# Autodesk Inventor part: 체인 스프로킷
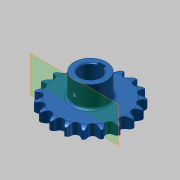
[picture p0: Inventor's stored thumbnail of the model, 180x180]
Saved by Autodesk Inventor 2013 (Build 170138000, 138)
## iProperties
Created: 2014-11
Part Number: 체인 스프로킷
Material: 강
Document SubType Name: Modeling
Designer: KYOUNG IL JANG
Density: 7.85 g/cm^3
Mass: 738.264 g
Surface Area: 236.923 cm^2
Volume: 94.0463 cm^3
CustomPartVersion: 1
Company: 한국ATC센터
Author: KYOUNG IL JANG
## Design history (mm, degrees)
sketch "이론적 톱니 프로파일"
  geometry: L1 (0, 0)-(0, 45.567); L2 (0, 0)-(14.795, 43.098); L3 (0, 45.567)-(14.795, 43.098); L4 (0, 45.567)-(5.661, 50.015); L5 (5.661, 50.015)-(-5.141, 45.406); L6 (-12.428, 43.493)-(-5.573, 46.417); L7 (-5.141, 45.406)-(-5.573, 46.417); L8 (5.573, 46.417)-(5.141, 45.406); L9 (0, 0)-(8.138, 48.771); A1 r 45.567 centre (0, 0) between (0, 45.567) and (14.795, 43.098); A2 r 49.445 centre (0, 0) between (7.302, 48.903) and (-7.302, 48.903); A3 r 4.545 centre (0, 45.567) between (-3.574, 42.758) and (3.574, 42.758); A4 r 7.453 centre (12.428, 43.493) between (7.302, 48.903) and (5.573, 46.417); A5 r 7.453 centre (-12.428, 43.493) between (-5.573, 46.417) and (-7.302, 48.903); A6 r 11.745 centre (5.661, 50.015) between (-5.141, 45.406) and (-3.574, 42.758); A7 r 11.745 centre (-5.661, 50.015) between (3.574, 42.758) and (5.141, 45.406); 2 further points
  constraints: 18 end point, 15 point on circle, 7 centre point, 3 coincident, 3 point on line, 3 symmetric about line, 3 tangent, 1 equal radius, 1 midpoint, 1 parallel, 1 vertical, 1 other
  dimensions: "d0" = 91.13301 diameter of A1 (computed from da_p, da_z); "d2" = 18.9474 deg angle of L2 L1 (computed from da_z); "d3" = 4.545 radius of A3 (= 0.5 x da_Dr + da_SC); "d10" = 128.158 deg angle of L4 L1 (computed from da_z); "d11" = 15.0526 deg angle of L5 L4 (computed from da_z); "d12" = 7.2 distance of L3.start L4.end (= 0.8 x da_Dr); "d13" = 11.745 distance of L4.end L5.end (= 1.3 x da_Dr + da_SC); "d14" = 12.6 distance of A4.centre L1.end (= 1.4 x da_Dr); "d23" = 4.5 distance from line of L9.end L3 (= da_Ha)
sketch "톱니 프로파일"
  geometry: L1 (0, 0)-(0, 45.567); L2 (0, 45.567)-(4.203, 43.837); L3 (0, 45.567)-(-4.203, 43.837); A1 r 4.545 centre (0, 45.567) between (-4.203, 43.837) and (4.203, 43.837); A2 r 22.68 centre (25.176, 35.206) between (7.12, 48.93) and (4.203, 43.837); A3 r 22.68 centre (-25.176, 35.206) between (-4.203, 43.837) and (-7.12, 48.93); A4 r 49.445 centre (0, 0) between (-7.12, 48.93) and (7.12, 48.93) reference; 1 further point
  constraints: 9 point on circle, 6 end point, 3 centre point, 2 tangent, 1 coincident, 1 equal radius, 1 vertical, 1 other
  dimensions: "d44" = 135.263 deg angle of L3 L2 (= da_Alfa); "d45" = 22.68 radius of A2 (= da_Re); "d46" = 4.545 radius of A1 (= da_Ri)
sketch "단면 프로파일"
  geometry: L1 (49.445, 0)-(-49.445, 0) reference; L2 (33.265, 6.65)-(-33.265, 6.65); L3 (-33.265, 6.65)-(-33.265, -6.65); L4 (-33.265, -6.65)-(33.265, -6.65); L5 (33.265, -6.65)-(33.265, 6.65); L6 (33.265, 6.65)-(49.445, 6.65); L7 (49.445, 6.65)-(49.445, -6.65); L8 (49.445, -6.65)-(33.265, -6.65); L9 (33.265, -6.65)-(33.265, 6.65); L10 (42.183, 6.65)-(0, 6.65); L11 (0, 6.65)-(0, -6.65); L12 (0, -6.65)-(42.183, -6.65); L13 (0, 6.65)-(0, -6.65); L14 (49.445, 4.775)-(49.445, -4.775); A1 r 15 centre (42.183, -8.35) between (49.445, 4.775) and (42.183, 6.65); A2 r 15 centre (42.183, 8.35) between (42.183, -6.65) and (49.445, -4.775); 2 further points
  constraints: 26 end point, 7 midpoint, 5 perpendicular, 4 parallel, 4 point on circle, 3 point on line, 3 symmetric about line, 2 centre point, 2 horizontal, 2 tangent, 1 collinear, 1 other
  dimensions: "d30" = 13.3 distance between parallel lines of L8 L6 (= da_Bf); "d31" = 66.53007 distance between parallel lines of L3 L5 (= da_Ds); "d32" = 13.3 distance between parallel lines of L4 L2 (= da_Bs); "d33" = 1.875 distance from line of L14.start L6 (= da_Ba); "d34" = 15 radius of A1 (= da_Rx); "d43" = 6.65 distance between parallel lines of L4 L1 (computed from da_k, da_pt, da_Bs)
revolve "슈라우드" stored, may be unused: angle "d36" = 90 deg
revolve "스트랜드" stored, may be unused: angle "d37" = 90 deg
extrude "이론적 톱니" cut sketch "이론적 톱니 프로파일" stored distance "d18" = 10; taper "d19" = 0 deg; dims "d49" = 0, "form_type" = 0 [user parameter]
extrude "톱니" cut sketch "톱니 프로파일" stored distance "d47" = 10; taper "d48" = 0 deg; dims "d50" = 10, "form_type" = 0 [user parameter]
node "타이밍 평면"
node "작업 평면3"
sketch "스케치5"
  geometry: C1 r 20 at (0, -45.567); 1 further point
  constraints: 1 centre point, 1 coincident
  dimensions: "d52" = 40 diameter of C1
extrude "돌출4" join sketch "스케치5" stored distance "d53" = 10; taper "d54" = 0 deg
sketch "스케치6"
  geometry: L1 (4, 11.843)-(4, 16.5); L2 (4, 16.5)-(-4, 16.5); L3 (-4, 16.5)-(-4, 11.843); A1 r 12.5 centre (0, 0) between (4, 11.843) and (-4, 11.843); 1 further point
  constraints: 6 end point, 2 parallel, 2 point on circle, 1 centre point, 1 coincident, 1 perpendicular, 1 vertical
  dimensions: "d55" = 25 diameter of A1; "d56" = 29 dimension on A1 L2 (computed from d55); "d57" = 8 distance of L1.end L2.end
extrude "돌출5" cut sketch "스케치6" stored distance "d58" = 10; taper "d59" = 0 deg
fillet "모깎기2" dims "d60" = 3
chamfer "모따기1" distance "d61" = 1; stored, may be unused: second distance "d62" = 2, angle "d63" = 45 deg
node "작업 평면4"
sketch "스케치7"
  geometry: L1 (-13.5, -13.3)-(13.5, -13.3) reference; 4 further points
  constraints: 1 vertical alignment
  dimensions: "d65" = 25 distance from line of point (0, 11.7) L1
hole "구멍1" sketch "스케치7" at (0, 11.7) diameter "d66" = 5; stored, may be unused: countersink angle "d70" = 90 deg, drill point angle "d72" = 118 deg; dims "d67" = 6, "d68" = 4, "d69" = 2, "d71" = 8
feature "스레드1" dims "d73" = 10, "d74" = 0
body "Solid1"
pattern_linear "스트랜드 패턴" dims "d40" = 24 (= da_pt)
pattern_circular "톱니 패턴" dims angle "d21" = 360 deg
other parameters: "da_p" = 15 [user parameter; used in 1 equation term], "da_Dr" = 9 [user parameter; used in 4 equation terms], "da_SC" = 0.045 [user parameter; used in 2 equation terms], "da_Ha" = 4.5 [user parameter; used in 1 equation term], "da_pt" = 24 [user parameter; used in 2 equation terms], "da_Bf" = 13.3 [user parameter; used in 1 equation term], "d28" = 0, "d29" = 0, "da_Ba" = 1.875 [user parameter; used in 1 equation term], "da_Rx" = 15 [user parameter; used in 1 equation term], "da_Ra" = 0.6 [user parameter], "da_Bs" = 13.3 [user parameter; used in 2 equation terms], "da_Ds" = 66.53007 [user parameter; used in 1 equation term], "d42" = 0, "da_Re" = 22.68 [user parameter; used in 1 equation term], "da_Ri" = 4.545 [user parameter; used in 1 equation term], "da_Alfa" = 135.263 deg [user parameter; used in 1 equation term]
